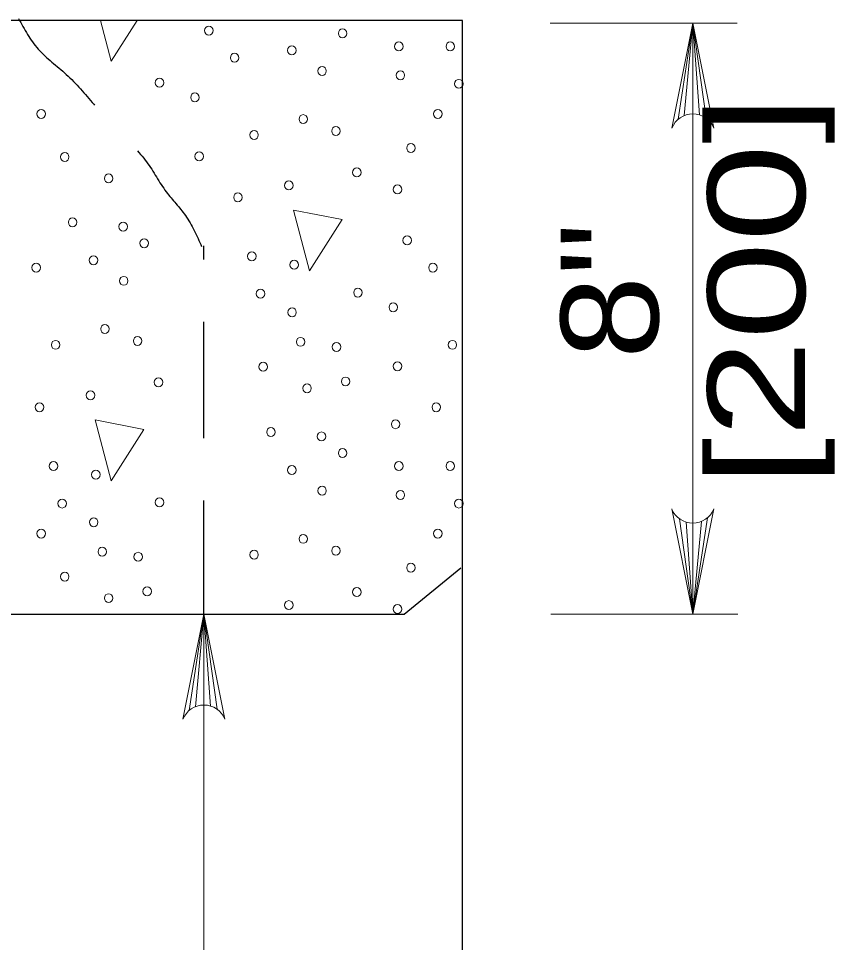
# Model space of a CAD drawing. Extents: x 1083.1 to 1117.1, y 697.4 to 719.4.
# Drawn here: x 1106.156 to 1107.46, y 704.837 to 706.315 of the extents above; entities that cross this region are included whole.
import ezdxf
from ezdxf.enums import TextEntityAlignment as Align

# ---------------------------------------------------------------- set-up
doc = ezdxf.new("R2010")
doc.units = 0
doc.header["$LTSCALE"] = 0.062
doc.linetypes.add('MEDIUM_DASHED', pattern=[4.5, 3, -1.5])
doc.layers.add('1', color=7, linetype='Continuous', lineweight=13)

msp = doc.modelspace()

# ---------------------------------------------------------------- linework, layer by layer
at = {"layer": '1'}
for p, q in [((1107.00575, 706.30817), (1107.305, 706.30817)), ((1107.21033, 706.15408), (1107.23392, 706.30817)), ((1107.22025, 706.15992), (1107.23392, 706.30817)), ((1107.23392, 706.16258), (1107.23392, 706.30817)), ((1107.24467, 706.16108), (1107.23392, 706.30817)), ((1107.25525, 706.15592), (1107.23392, 706.30817)), ((1107.23392, 706.30817), (1107.23392, 705.36225)), ((1107.21258, 705.51458), (1107.23392, 705.36225)), ((1107.22317, 705.50942), (1107.23392, 705.36225)), ((1107.2575, 705.51633), (1107.23392, 705.36225)), ((1107.24758, 705.5105), (1107.23392, 705.36225)), ((1107.23392, 705.50783), (1107.23392, 705.36225)), ((1106.42858, 705.20808), (1106.45208, 705.36217)), ((1106.43842, 705.21392), (1106.45208, 705.36217)), ((1106.45208, 705.36217), (1106.45208, 701.25917)), ((1106.45208, 705.21667), (1106.45208, 705.36217)), ((1106.46283, 705.21508), (1106.45208, 705.36217)), ((1106.47342, 705.20992), (1106.45208, 705.36217)), ((1107.00675, 705.36217), (1107.306, 705.36217))]:
    msp.add_line(p, q, dxfattribs=at)
at = {"layer": '1', "linetype": 'MEDIUM_DASHED', "lineweight": 25}
msp.add_line((1106.45208, 705.35783), (1106.45208, 705.95167), dxfattribs=at)
at = {"layer": '1', "lineweight": 25}
for p, q in [((1106.77217, 705.36217), (1106.86283, 705.43633)), ((1106.86575, 701.19417), (1106.86575, 705.43083))]:
    msp.add_line(p, q, dxfattribs=at)
for points in [[(1106.86575, 705.43083), (1106.86575, 706.31208), (1101.2135, 706.31208)], [(1101.2135, 705.44708), (1101.31708, 705.36217), (1106.77217, 705.36217)]]:
    msp.add_lwpolyline(points, dxfattribs=at)
at = {"layer": '1'}
for points in [[(1106.28683, 706.31217), (1106.30392, 706.24717), (1106.34525, 706.31217)], [(1107.20025, 706.14), (1107.23392, 706.30817), (1107.26758, 706.14)], [(1107.26758, 705.5305), (1107.23392, 705.36225), (1107.20025, 705.5305)], [(1106.41842, 705.194), (1106.45208, 705.36217), (1106.48575, 705.194)]]:
    msp.add_lwpolyline(points, dxfattribs=at)
for points in [[(1106.5955, 706.00867), (1106.62117, 705.91142), (1106.67333, 705.99358)], [(1106.27833, 705.67292), (1106.30392, 705.5755), (1106.35625, 705.65767)]]:
    msp.add_lwpolyline(points, close=True, dxfattribs=at)
for centre, start, end in [((1107.23396, 706.12638), 22.08782, 157.91395), ((1107.23388, 705.54408), 202.08782, 337.91395), ((1106.45213, 705.1804), 22.08782, 157.91395)]:
    msp.add_arc(centre, 0.03631, start, end, dxfattribs=at)
for centre in [(1106.45998, 706.29609), (1106.67382, 706.29156), (1106.76375, 706.27068), (1106.84601, 706.27068), (1106.50111, 706.25254), (1106.59273, 706.26435), (1106.64099, 706.23139), (1106.76629, 706.22445), (1106.38115, 706.21264), (1106.8597, 706.21085), (1106.43767, 706.18907), (1106.19184, 706.16277), (1106.61102, 706.15432), (1106.82624, 706.16277), (1106.66325, 706.13529), (1106.53219, 706.12896), (1106.78315, 706.10808), (1106.22953, 706.09387), (1106.44454, 706.09471), (1106.69661, 706.06907), (1106.29974, 706.05939), (1106.58786, 706.0482), (1106.76174, 706.04187), (1106.50645, 706.02917), (1106.24211, 705.98931), (1106.32295, 705.98232), (1106.77718, 705.96027), (1106.35662, 705.95573), (1106.27553, 705.92853), (1106.52881, 705.93485), (1106.18391, 705.91672), (1106.59643, 705.92125), (1106.81831, 705.91672), (1106.32379, 705.89556), (1106.5425, 705.87502), (1106.69836, 705.87681), (1106.75487, 705.85325), (1106.59299, 705.84508), (1106.29382, 705.81849), (1106.34605, 705.79946), (1106.60674, 705.79795), (1106.21499, 705.79314), (1106.6641, 705.78972), (1106.8494, 705.79314), (1106.54673, 705.75804), (1106.76174, 705.75888), (1106.37941, 705.73325), (1106.61694, 705.72356), (1106.67864, 705.73448), (1106.27066, 705.71237), (1106.18925, 705.69334), (1106.82365, 705.69334), (1106.75862, 705.66614), (1106.55932, 705.65349), (1106.64015, 705.64649), (1106.67382, 705.61991), (1106.21161, 705.59903), (1106.59273, 705.59271), (1106.76375, 705.59903), (1106.84601, 705.59903), (1106.27923, 705.58543), (1106.64099, 705.55974), (1106.76629, 705.5528), (1106.2253, 705.5392), (1106.38115, 705.54099), (1106.8597, 705.5392), (1106.27579, 705.50925), (1106.19184, 705.49112), (1106.82624, 705.49112), (1106.61102, 705.48267), (1106.28954, 705.46213), (1106.53219, 705.45731), (1106.66325, 705.46364), (1106.3469, 705.4539), (1106.78315, 705.43643), (1106.22953, 705.42222), (1106.36143, 705.39865), (1106.69661, 705.39742), (1106.29974, 705.38774), (1106.58786, 705.37655), (1106.76174, 705.37022)]:
    msp.add_ellipse(centre, major_axis=(0, 0.00718), ratio=0.944544, dxfattribs=at)
at = {"layer": '1', "linetype": 'MEDIUM_DASHED', "lineweight": 25}
msp.add_spline([(1106.15558, 706.31542), (1106.187, 706.2665), (1106.23192, 706.226), (1106.276, 706.17808), (1106.31825, 706.13192), (1106.3605, 706.08583), (1106.39192, 706.03783), (1106.42242, 706.00025), (1106.44842, 705.95042)], degree=3, dxfattribs=at)

# ---------------------------------------------------------------- texts
at = {"layer": '1'}
for s, width, p in [('[200]', 1.35, (1107.41342, 705.87958)), ('8"', 1.15, (1107.17875, 705.87958))]:
    msp.add_text(s, height=0.156, rotation=90, dxfattribs=dict(at, width=width)).set_placement(p, align=Align.CENTER)

doc.saveas('drawing.dxf')
